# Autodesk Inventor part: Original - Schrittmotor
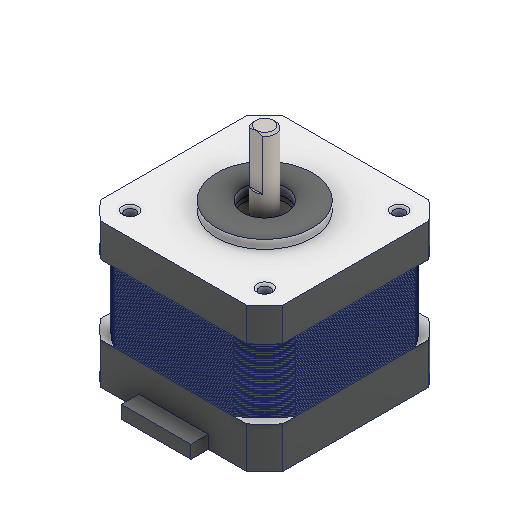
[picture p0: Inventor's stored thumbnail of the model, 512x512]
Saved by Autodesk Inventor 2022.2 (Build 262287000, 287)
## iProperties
Created: 2024-09
Part Number: Original - Schrittmotor
Material: Generico
Document SubType Name: Modeling
Designer: 18907419
Density: 1 g/cm^3
Appearance: Default
Author: 18907419
Revision Number: ANY
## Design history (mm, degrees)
feature "Fase2"
feature "Schnitt-Linear austragen1[2]" [Fase]
feature "Fase1"
feature "Schnitt-Linear austragen4" [Fase]
feature "Schnitt-Austragung1" [Fase]
node "Solido1"
node "Solido2"
node "Solido3"
node "Solido4"
node "Solido5"
